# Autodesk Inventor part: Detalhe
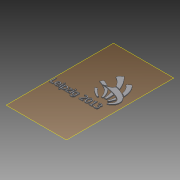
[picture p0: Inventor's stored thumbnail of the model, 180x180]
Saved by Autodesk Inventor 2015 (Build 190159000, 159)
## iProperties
Created: 2015-05
Part Number: Detalhe
Material: Generic
Document SubType Name: Modeling
Designer: TREINA1
Density: 1 g/cm^3
Appearance: Default
Author: TREINA1
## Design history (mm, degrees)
sketch "Sketch1"
  geometry: L1 (-18.249, -1.152)-(10.974, -1.152); L2 (10.974, -1.152)-(10.974, -5.718); L3 (10.974, -5.718)-(-18.249, -5.718); L4 (-18.249, -5.718)-(-18.249, -1.152); L5 (2.715, 1.535)-(2.302, 1.01); L6 (-1.368, 5.063)-(-1.376, 5.065); L7 (-1.743, 5.001)-(-1.994, 4.845); L8 (-2.179, 4.777)-(-2.669, 4.698); L9 (3.636, 2.058)-(4.419, 2.305); L10 (4.969, 2.343)-(5.992, 2.343); L11 (6.938, 2.012)-(7.572, 1.615); L12 (1.752, 7.409)-(-1.566, 7.881); L13 (0.093, 8.777)-(-1.743, 8.025); L14 (4.153, 6.9)-(5.915, 6.428); L15 (4.989, 10.506)-(2.813, 10.994); L16 (2.813, 10.994)-(2.715, 10.836); L17 (0.151, 17.853)-(0.093, 17.592); L18 (-1.553, 16.047)-(-1.7, 15.219); A1 r 11.444 centre (6.381, 11.702) between (-2.669, 4.698) and (2.302, 1.01); A2 r 13.446 centre (9.286, 13.267) between (-1.368, 5.063) and (2.715, 1.535); A3 r 0.5 centre (-1.48, 4.576) between (-1.376, 5.065) and (-1.743, 5.001); A4 r 1.624 centre (6.733, 0.146) between (8.345, 0.339) and (8.149, 0.94); A5 r 8.772 centre (-4.823, -0.264) between (3.636, 2.058) and (-1.566, 7.881); A6 r 9.996 centre (-5.398, 0.424) between (4.419, 2.305) and (1.752, 7.409); A7 r 16.324 centre (-8.548, -5.073) between (0.093, 8.777) and (-3.353, 10.403); A8 r 22.66 centre (-10.328, -12.947) between (-1.743, 8.025) and (-4.32, 8.903); A9 r 0.967 centre (-4.756, 9.766) between (-4.32, 8.903) and (-3.79, 9.802); A10 r 2.408 centre (-2.015, 8.4) between (-3.353, 10.403) and (-3.624, 10.193); A11 r 0.5 centre (-3.29, 9.821) between (-3.624, 10.193) and (-3.79, 9.802); A12 r 0.5 centre (-2.258, 5.27) between (-2.179, 4.777) and (-1.994, 4.845); A13 r 20.756 centre (-15.742, 0.985) between (4.969, 2.343) and (4.153, 6.9); A14 r 22.143 centre (-16.091, 3.974) between (5.992, 2.343) and (5.915, 6.428); A15 r 18.559 centre (-12.488, 4.263) between (4.989, 10.506) and (0.151, 17.853); A16 r 10.472 centre (-6.537, 5.931) between (2.715, 10.836) and (-1.7, 15.219); A17 r 1.686 centre (-1.308, 18.529) between (-0.882, 16.898) and (0.093, 17.592); A18 r 1.146 centre (-0.424, 15.847) between (-0.882, 16.898) and (-1.553, 16.047); A19 r 10.588 centre (-2.744, 6.298) between (6.938, 2.012) and (7.82, 5.58); A20 r 13.794 centre (-4.205, 8.798) between (7.572, 1.615) and (8.966, 4.698); A21 r 3.925 centre (6.04, 2.082) between (8.966, 4.698) and (7.82, 5.58); A22 r 14.728 centre (1.154, -3.775) between (9.58, 8.304) and (7.648, 9.443); A23 r 7.299 centre (0.434, 8.335) between (7.648, 9.443) and (4.614, 14.318); A24 r 11.857 centre (-2.275, 8.118) between (9.58, 8.304) and (8.088, 13.88); A25 r 6.454 centre (2.447, 10.744) between (8.088, 13.88) and (6.259, 15.951); A26 r 0.518 centre (5.741, 15.955) between (5.986, 15.498) and (6.259, 15.951); A27 r 4.174 centre (7.957, 11.819) between (5.986, 15.498) and (4.614, 14.318); A28 r 4.301 centre (5.872, 4.589) between (8.149, 0.94) and (9.667, 2.564); A29 r 1.92 centre (7.973, 3.468) between (9.667, 2.564) and (9.489, 4.645); A30 r 5.002 centre (5.539, 1.577) between (9.489, 4.645) and (7.418, 6.213); A31 r 25.18 centre (-2.04, -17.124) between (7.418, 6.213) and (4.884, 7.086); A32 r 31.928 centre (-3.896, -23.612) between (4.884, 7.086) and (-0.406, 8.125); A33 r 22.59 centre (-8.177, 29.336) between (-0.406, 8.125) and (1.55, 8.948); A34 r 2.322 centre (0.55, 11.043) between (1.55, 8.948) and (2.125, 9.338); A35 r 3.881 centre (-0.508, 12.189) between (2.125, 9.338) and (3.021, 10.573); A36 r 16.193 centre (0.268, -5.384) between (8.765, 8.4) and (3.021, 10.573); A37 r 5.642 centre (5.911, 3.534) between (11.233, 5.406) and (8.765, 8.4); A38 r 4.402 centre (6.957, 4.361) between (11.023, 2.673) and (11.233, 5.406); A39 r 5.253 centre (6.42, 5.203) between (9.785, 1.17) and (11.023, 2.673); A40 r 4.589 centre (6.811, 4.664) between (8.345, 0.339) and (9.785, 1.17)
  constraints: 82 point on circle, 40 centre point, 28 end point, 15 tangent, 1 horizontal, 2 other
  dimensions: "d24" = 0.5 radius of A3; "d25" = 0.5 radius of A11; "d26" = 0.5 radius of A12
workplane "Work Plane1"
sketch "Sketch2"
  geometry: 1 further point
extrude "Extrusion1" new body sketch "Sketch1" distance "d39" = 0.5; taper "d40" = 0 deg
body "Solid1"
other parameters: "d38" = -1
